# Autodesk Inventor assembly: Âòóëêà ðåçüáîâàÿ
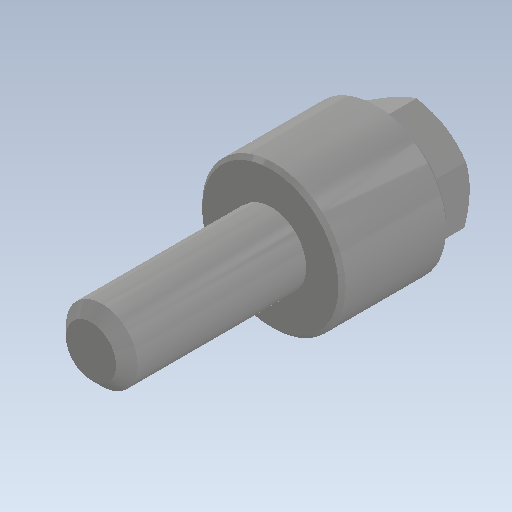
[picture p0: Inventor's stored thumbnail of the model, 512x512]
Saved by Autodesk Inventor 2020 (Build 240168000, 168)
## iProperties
Created: 1900-01
Part Number: Âòóëêà ðåçüáîâàÿ
Document SubType Name: Assembly
Designer: bruno
Author: bruno
Revision Number: ANYUNSPECIFIED
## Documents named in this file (3)
- C:\Users\bruno\Documents\1-Cours-2022-23\1SI\2. Cinématique\Hoverboard\Inventor-Hoverboard\Axe-1.iam
- C:\Users\bruno\Documents\1-Cours-2022-23\1SI\2. Cinématique\Hoverboard\Inventor-Hoverboard\Vis.ipt
- C:\Users\bruno\Documents\1-Cours-2022-23\1SI\2. Cinématique\Hoverboard\Inventor-Hoverboard\Pièce88.ipt
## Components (2 placed, 2 different names)
1. 9
2. Pièce88
